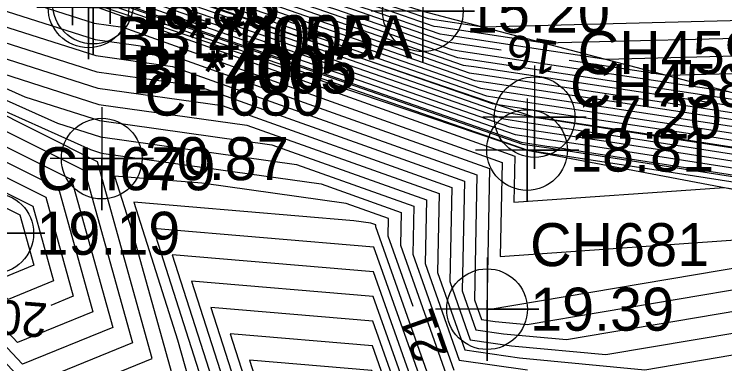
# Model space of a CAD drawing. Extents: x 2531902 to 2533249, y 715219 to 716099.
# Drawn here: x 2532709.09 to 2532750.37, y 715611.98 to 715632.29 of the extents above; entities that cross this region are included whole.
import ezdxf

# ---------------------------------------------------------------- set-up
doc = ezdxf.new("R2010")
doc.units = 0
for name, color, linetype in [('DTM Contours Major', 7, 'Continuous'), ('DTM Contours Major Text', 7, 'Continuous'), ('DTM Contours Minor', 7, 'Continuous'), ('Exist DTM Breakline', 7, 'Continuous'), ('Exist DTM Breakline Cogo Comment', 7, 'Continuous'), ('Exist DTM Breakline Cogo Elevation', 7, 'Continuous'), ('Exist DTM Breakline Cogo Number', 7, 'Continuous'), ('Exist DTM Breakline Cogo Point CELL', 7, 'Continuous'), ('Exist DTM Breakline Underwater', 7, 'Continuous'), ('Exist DTM Breakline Underwater Cogo Elevation', 7, 'Continuous'), ('Exist DTM Breakline Underwater Cogo Point CELL', 7, 'Continuous'), ('Exist DTM QL2 LIDAR Elevation Point', 7, 'Continuous'), ('Exist DTM Regular Point CELL', 7, 'Continuous'), ('Exist DTM Regular Point Cogo Elevation', 7, 'Continuous'), ('Exist DTM Regular Point Cogo Number', 7, 'Continuous'), ('Exist Hydro Stream or Body of Water', 7, 'Continuous'), ('Scratch_Level_2', 7, 'Continuous')]:
    doc.layers.add(name, color=color, linetype=linetype)

msp = doc.modelspace()

# ---------------------------------------------------------------- linework, layer by layer
at = {"layer": 'DTM Contours Major'}
for points in [[(2532737.37, 715630.195), (2532734.519, 715630.627), (2532734.167, 715630.68), (2532728.764, 715632.559), (2532713.824, 715637.321), (2532713.421, 715637.449), (2532709.196, 715638.824), (2532697.196, 715643.047), (2532697.098, 715643.082), (2532696.035, 715644.027), (2532679.899, 715666.702), (2532679.893, 715666.711), (2532679.876, 715666.752), (2532679.875, 715666.753), (2532679.797, 715667.006), (2532679.994, 715666.896), (2532680.065, 715666.76), (2532689.19, 715656.805), (2532699.24, 715647.16), (2532699.515, 715647.106)], [(2532674.529, 715657.71), (2532672.706, 715658.283), (2532669.358, 715655.677), (2532669.391, 715655.408), (2532669.64, 715655.324), (2532669.93, 715655.106), (2532682.035, 715650.435), (2532694.89, 715638.9), (2532696.316, 715638.261), (2532713.679, 715632.717), (2532713.962, 715632.678), (2532738.178, 715624.046), (2532738.122, 715621.369), (2532750.341, 715622.225), (2532752.309, 715621.919)], [(2532685.255, 715654.828), (2532691.3, 715646.332), (2532696.58, 715641.634), (2532697.068, 715641.462), (2532704.54, 715638.833), (2532713.504, 715635.916), (2532714.36, 715635.643), (2532723.662, 715632.678), (2532735.847, 715628.442), (2532736.64, 715628.322), (2532753.273, 715625.799), (2532757.258, 715625.179), (2532759.557, 715625.11), (2532775.441, 715624.38), (2532776.659, 715624.324)], [(2532683.669, 715652.707), (2532686.565, 715648.638), (2532696.063, 715640.186), (2532696.941, 715639.877), (2532699.885, 715638.841), (2532713.588, 715634.382), (2532714.896, 715633.965), (2532718.561, 715632.797), (2532737.526, 715626.203), (2532738.761, 715626.016), (2532745.314, 715625.023), (2532758.183, 715623.02), (2532765.608, 715622.796), (2532771.866, 715622.509), (2532775.8, 715622.328)], [(2532674.126, 715647.354), (2532676.074, 715645.889), (2532680.793, 715644.068), (2532685.805, 715639.571), (2532705.874, 715630.573), (2532713.943, 715627.997), (2532721.165, 715626.984), (2532734.505, 715622.229), (2532734.391, 715616.753), (2532735.587, 715613.371), (2532737.979, 715613.025), (2532743.455, 715612.508), (2532753.726, 715614.247), (2532759.739, 715613.652), (2532760.112, 715613.48)], [(2532713.794, 715641.93), (2532723.088, 715642.496), (2532736.736, 715641.742), (2532744.32, 715638.604), (2532751.762, 715638.071), (2532755.947, 715636.768), (2532756.057, 715636.734), (2532756.721, 715636.63), (2532756.752, 715636.632), (2532759.128, 715636.781), (2532769.239, 715634.791), (2532776.683, 715633.031), (2532755.339, 715628.939), (2532747.02, 715628.731), (2532741.325, 715629.595)], [(2532683.727, 715635.961), (2532692.276, 715630.998), (2532710.916, 715621.657), (2532712.519, 715615.898), (2532711.223, 715615.369)], [(2532732.259, 715615.307), (2532730.812, 715619.4), (2532730.833, 715620.412), (2532728.367, 715621.291), (2532719.991, 715622.465), (2532714.911, 715622.89), (2532715.925, 715619.72), (2532718.245, 715611.384), (2532714.855, 715610), (2532715.256, 715604.744)], [(2532732.381, 715607.491), (2532729.917, 715614.457), (2532720.511, 715615.244), (2532722.885, 715607.822), (2532723.016, 715600.82), (2532724.345, 715598.612)]]:
    msp.add_lwpolyline(points, dxfattribs=at)
at = {"layer": 'DTM Contours Minor'}
for points in [[(2532636.7, 715718.732), (2532648.882, 715711.393), (2532650.176, 715710.428), (2532650.296, 715710.159), (2532650.961, 715708.731), (2532650.355, 715708.634), (2532649.557, 715698.18), (2532650.088, 715686.722), (2532650.205, 715682.83), (2532652.525, 715675.584), (2532660.005, 715667.15), (2532660.202, 715660.027), (2532660.105, 715659.951), (2532661.242, 715650.715), (2532669.816, 715647.839), (2532679.761, 715640.359), (2532680.048, 715640.248), (2532680.354, 715639.974), (2532711.609, 715625.96), (2532714.102, 715625.164), (2532725.486, 715623.568), (2532732.302, 715621.139), (2532732.243, 715618.341), (2532734.625, 715611.607)], [(2532680.17, 715665.452), (2532695.088, 715644.488), (2532696.994, 715642.792), (2532697.17, 715642.73), (2532708.265, 715638.826), (2532713.437, 715637.143), (2532713.931, 715636.985), (2532727.744, 715632.583), (2532734.503, 715630.233), (2532734.943, 715630.166), (2532750.583, 715627.794)], [(2532680.44, 715664.202), (2532694.141, 715644.949), (2532696.891, 715642.503), (2532697.145, 715642.413), (2532707.334, 715638.828), (2532713.454, 715636.836), (2532714.038, 715636.65), (2532726.723, 715632.606), (2532734.839, 715629.785), (2532735.368, 715629.705), (2532754.145, 715626.858), (2532756.43, 715626.915), (2532765.962, 715628.742), (2532762.782, 715626.183), (2532777.586, 715625.503), (2532778.432, 715625.464), (2532781.602, 715625.476), (2532796.599, 715625.363), (2532796.712, 715625.362), (2532796.887, 715625.399), (2532820.079, 715630.296)], [(2532680.711, 715662.952), (2532693.194, 715645.41), (2532696.787, 715642.213), (2532697.119, 715642.096), (2532706.403, 715638.829), (2532713.471, 715636.529), (2532714.146, 715636.314), (2532725.703, 715632.63), (2532735.175, 715629.337), (2532735.792, 715629.244), (2532756.457, 715626.11), (2532756.888, 715626.043), (2532757.137, 715626.036), (2532776.871, 715625.128), (2532778.124, 715625.071), (2532782.819, 715625.089), (2532796.483, 715624.986), (2532796.744, 715624.984), (2532797.148, 715625.069), (2532818.278, 715629.531)], [(2532680.982, 715661.701), (2532692.247, 715645.871), (2532696.684, 715641.923), (2532697.094, 715641.779), (2532705.471, 715638.831), (2532713.487, 715636.222), (2532714.253, 715635.978), (2532724.683, 715632.654), (2532735.511, 715628.89), (2532736.216, 715628.783), (2532754.865, 715625.955), (2532757.073, 715625.611), (2532758.347, 715625.573), (2532776.156, 715624.754), (2532777.816, 715624.678), (2532784.036, 715624.702), (2532796.367, 715624.609), (2532796.776, 715624.606), (2532797.409, 715624.739), (2532816.477, 715628.766)], [(2532681.524, 715659.201), (2532690.353, 715646.793), (2532696.477, 715641.344), (2532697.043, 715641.145), (2532703.609, 715638.834), (2532713.521, 715635.609), (2532714.467, 715635.307), (2532722.642, 715632.701), (2532736.183, 715627.994), (2532737.064, 715627.861), (2532751.681, 715625.644), (2532757.443, 715624.748), (2532760.767, 715624.647), (2532774.726, 715624.006), (2532777.201, 715623.892), (2532786.471, 715623.928), (2532796.136, 715623.855), (2532796.841, 715623.85), (2532797.93, 715624.08), (2532812.876, 715627.235)], [(2532681.795, 715657.95), (2532689.406, 715647.255), (2532696.373, 715641.055), (2532697.018, 715640.828), (2532702.678, 715638.836), (2532713.538, 715635.302), (2532714.575, 715634.971), (2532721.622, 715632.725), (2532736.519, 715627.547), (2532737.489, 715627.399), (2532750.09, 715625.489), (2532757.628, 715624.316), (2532761.978, 715624.184), (2532774.011, 715623.631), (2532776.893, 715623.499), (2532787.688, 715623.54), (2532796.02, 715623.478), (2532796.873, 715623.471), (2532798.191, 715623.75), (2532811.075, 715626.47)], [(2532682.066, 715656.7), (2532688.459, 715647.716), (2532696.27, 715640.765), (2532696.992, 715640.511), (2532701.747, 715638.838), (2532713.554, 715634.995), (2532714.682, 715634.636), (2532720.601, 715632.749), (2532736.855, 715627.099), (2532737.913, 715626.938), (2532748.498, 715625.333), (2532757.813, 715623.884), (2532763.188, 715623.722), (2532773.296, 715623.257), (2532776.585, 715623.106), (2532788.906, 715623.153), (2532795.904, 715623.101), (2532796.905, 715623.093), (2532798.452, 715623.42), (2532809.275, 715625.705)], [(2532682.336, 715655.45), (2532687.512, 715648.177), (2532696.166, 715640.475), (2532696.967, 715640.194), (2532700.816, 715638.839), (2532713.571, 715634.688), (2532714.789, 715634.3), (2532719.581, 715632.773), (2532737.191, 715626.651), (2532738.337, 715626.477), (2532746.906, 715625.178), (2532757.998, 715623.452), (2532764.398, 715623.259), (2532772.581, 715622.883), (2532776.277, 715622.713), (2532790.123, 715622.766), (2532795.789, 715622.724), (2532796.937, 715622.715), (2532798.713, 715623.09), (2532807.474, 715624.94)], [(2532681.549, 715654.816), (2532682.878, 715652.949), (2532685.618, 715649.099), (2532695.959, 715639.896), (2532696.916, 715639.56), (2532698.953, 715638.843), (2532713.604, 715634.075), (2532715.003, 715633.629), (2532717.54, 715632.82), (2532737.862, 715625.756), (2532739.186, 715625.555), (2532743.722, 715624.867), (2532758.368, 715622.588), (2532766.819, 715622.333), (2532771.15, 715622.134), (2532775.661, 715621.927), (2532792.558, 715621.992), (2532795.557, 715621.969), (2532797.001, 715621.958), (2532799.234, 715622.43), (2532803.873, 715623.409)], [(2532681.7, 715653.735), (2532683.149, 715651.699), (2532684.671, 715649.56), (2532695.856, 715639.607), (2532696.89, 715639.243), (2532698.022, 715638.844), (2532713.621, 715633.768), (2532715.111, 715633.293), (2532716.52, 715632.844), (2532738.198, 715625.308), (2532739.61, 715625.094), (2532742.13, 715624.712), (2532758.553, 715622.157), (2532768.029, 715621.871), (2532770.435, 715621.76), (2532775.353, 715621.534), (2532793.775, 715621.605), (2532795.442, 715621.592), (2532797.033, 715621.58), (2532799.495, 715622.1), (2532802.072, 715622.644)], [(2532681.851, 715652.654), (2532683.42, 715650.449), (2532683.724, 715650.021), (2532695.752, 715639.317), (2532696.865, 715638.926), (2532697.091, 715638.846), (2532713.638, 715633.461), (2532715.218, 715632.958), (2532715.5, 715632.868), (2532738.534, 715624.86), (2532740.034, 715624.633), (2532740.538, 715624.556), (2532758.738, 715621.725), (2532769.239, 715621.408), (2532769.72, 715621.386), (2532775.045, 715621.141), (2532794.993, 715621.218), (2532795.326, 715621.215), (2532797.066, 715621.202), (2532799.756, 715621.77), (2532800.271, 715621.879), (2532825.827, 715627.523)], [(2532682.001, 715651.572), (2532682.777, 715650.482), (2532690.122, 715643.946), (2532695.649, 715639.028), (2532696.16, 715638.848), (2532705.016, 715635.966), (2532713.655, 715633.155), (2532714.479, 715632.892), (2532737.701, 715624.819), (2532738.87, 715624.413), (2532738.946, 715624.401), (2532745.88, 715623.322), (2532758.923, 715621.293), (2532766.449, 715621.066), (2532770.449, 715620.945), (2532774.737, 715620.748), (2532790.801, 715620.81), (2532796.21, 715620.83), (2532797.098, 715620.824), (2532798.47, 715621.114), (2532803.901, 715622.313)], [(2532681.787, 715649.161), (2532693.073, 715639.034), (2532698.228, 715636.723), (2532713.731, 715631.773), (2532715.403, 715631.539), (2532737.443, 715623.682), (2532737.33, 715618.219), (2532754.561, 715619.426), (2532758.918, 715620.164), (2532759.276, 715620.128), (2532759.832, 715619.872), (2532762.685, 715620.327), (2532772.87, 715620.019), (2532774.121, 715619.962), (2532778.811, 715619.98), (2532783.105, 715619.996), (2532796.357, 715619.409), (2532797.382, 715619.588), (2532797.854, 715619.53), (2532798.133, 715619.713), (2532799.275, 715620.232), (2532807.884, 715622.457)], [(2532713.029, 715641.979), (2532716.741, 715641.26), (2532724.694, 715641.744), (2532736.373, 715641.099), (2532747.184, 715636.626), (2532755.897, 715636.002), (2532769.535, 715632.777), (2532754.794, 715629.951), (2532743.458, 715629.668), (2532734.095, 715631.088), (2532733.831, 715631.128), (2532729.784, 715632.535), (2532713.717, 715637.657), (2532713.404, 715637.756), (2532710.127, 715638.823), (2532697.221, 715643.364), (2532697.201, 715643.371), (2532696.982, 715643.566), (2532693.501, 715648.458), (2532695.572, 715646.199), (2532697.642, 715644.211), (2532704.931, 715642.789), (2532712.237, 715641.951), (2532713.029, 715641.979)], [(2532681.538, 715647.888), (2532691.256, 715639.168), (2532700.139, 715635.185), (2532713.784, 715630.829), (2532716.843, 715630.4), (2532736.709, 715623.319), (2532736.539, 715615.164), (2532736.549, 715615.135), (2532736.57, 715615.132), (2532736.617, 715615.128), (2532757.62, 715618.685), (2532759.392, 715618.509), (2532762.143, 715617.241), (2532773.58, 715619.066), (2532773.975, 715619.47), (2532774.163, 715619.461), (2532795.746, 715618.505), (2532797.59, 715618.827), (2532798.439, 715618.722), (2532798.941, 715619.051), (2532800.996, 715619.985), (2532816.486, 715623.99)], [(2532681.29, 715646.615), (2532689.439, 715639.303), (2532702.051, 715633.648), (2532713.837, 715629.885), (2532718.284, 715629.262), (2532735.974, 715622.956), (2532735.823, 715615.694), (2532736.229, 715614.547), (2532737.039, 715614.43), (2532738.896, 715614.255), (2532756.322, 715617.206), (2532759.507, 715616.89), (2532764.454, 715614.609), (2532771.942, 715615.804), (2532774.584, 715618.512), (2532775.847, 715618.455), (2532795.135, 715617.6), (2532797.797, 715618.066), (2532799.024, 715617.915), (2532799.75, 715618.389), (2532802.717, 715619.738)], [(2532681.042, 715645.341), (2532687.622, 715639.437), (2532703.963, 715632.11), (2532713.89, 715628.941), (2532719.724, 715628.123), (2532735.24, 715622.592), (2532735.107, 715616.223), (2532735.908, 715613.959), (2532737.509, 715613.727), (2532741.176, 715613.381), (2532755.024, 715615.726), (2532759.623, 715615.271), (2532766.765, 715611.978), (2532770.304, 715612.543), (2532775.194, 715617.554), (2532777.532, 715617.449), (2532794.524, 715616.696), (2532798.005, 715617.305), (2532799.61, 715617.107), (2532800.558, 715617.728), (2532804.439, 715619.492)], [(2532680.545, 715642.795), (2532683.988, 715639.705), (2532707.786, 715629.035), (2532713.996, 715627.053), (2532722.605, 715625.845), (2532733.771, 715621.865), (2532733.675, 715617.282), (2532735.267, 715612.783), (2532738.448, 715612.322), (2532745.734, 715611.634), (2532752.429, 715612.768), (2532759.855, 715612.033), (2532764.702, 715609.798)], [(2532716.602, 715641.188), (2532719.688, 715640.59), (2532726.3, 715640.993), (2532736.01, 715640.456), (2532750.047, 715634.648), (2532754.857, 715634.304), (2532762.386, 715632.523), (2532754.248, 715630.963), (2532739.896, 715630.605), (2532733.671, 715631.549), (2532733.495, 715631.576), (2532730.804, 715632.511), (2532713.61, 715637.992), (2532713.387, 715638.063), (2532711.058, 715638.821), (2532700.961, 715642.374), (2532712.558, 715641.045), (2532716.602, 715641.188)], [(2532720.174, 715640.397), (2532722.634, 715639.92), (2532727.906, 715640.241), (2532735.646, 715639.814), (2532752.91, 715632.67), (2532753.818, 715632.605), (2532755.238, 715632.27), (2532753.703, 715631.975), (2532736.334, 715631.542), (2532733.246, 715632.01), (2532733.159, 715632.024), (2532731.825, 715632.487), (2532713.502, 715638.328), (2532713.37, 715638.37), (2532711.989, 715638.819), (2532706.002, 715640.926), (2532712.879, 715640.138), (2532720.174, 715640.397)], [(2532680.227, 715639.754), (2532680.748, 715639.451), (2532713.166, 715623.206), (2532715.954, 715613.19), (2532709.845, 715610.696), (2532701.165, 715619.935), (2532698.662, 715621.232), (2532689.962, 715621.442), (2532684.167, 715629.759), (2532680.227, 715639.754)], [(2532682.171, 715639.84), (2532709.697, 715627.498), (2532714.049, 715626.108), (2532724.046, 715624.707), (2532733.036, 715621.502), (2532732.959, 715617.812), (2532734.946, 715612.195), (2532738.918, 715611.62)], [(2532681.394, 715638.49), (2532684.591, 715636.634), (2532712.416, 715622.69), (2532714.809, 715614.092), (2532709.566, 715611.952), (2532702.115, 715619.882), (2532697.57, 715622.237), (2532689.936, 715622.421), (2532684.851, 715629.719), (2532681.394, 715638.49)], [(2532682.561, 715637.226), (2532688.433, 715633.816), (2532711.666, 715622.174), (2532713.664, 715614.995), (2532709.286, 715613.208), (2532703.065, 715619.83), (2532696.478, 715623.242), (2532689.91, 715623.401), (2532685.535, 715629.68), (2532682.561, 715637.226)], [(2532684.894, 715634.697), (2532696.119, 715628.18), (2532710.166, 715621.141), (2532711.374, 715616.801), (2532708.727, 715615.72), (2532704.965, 715619.724), (2532694.294, 715625.252), (2532689.858, 715625.359), (2532686.903, 715629.6), (2532684.894, 715634.697)], [(2532686.061, 715633.433), (2532699.961, 715625.363), (2532709.416, 715620.625), (2532710.229, 715617.704), (2532708.447, 715616.976), (2532705.916, 715619.671), (2532693.202, 715626.258), (2532689.832, 715626.339), (2532687.587, 715629.561), (2532686.061, 715633.433)], [(2532711.498, 715610), (2532717.1, 715612.287), (2532713.917, 715623.722), (2532704.007, 715628.688), (2532713.521, 715624.423), (2532714.154, 715624.22), (2532726.927, 715622.429), (2532731.567, 715620.775), (2532731.527, 715618.87), (2532734.305, 715611.019)], [(2532721.419, 715597.161), (2532729.966, 715582.968), (2532738.612, 715591.711), (2532738.691, 715600.338), (2532738.752, 715609.106), (2532733.664, 715609.843), (2532730.096, 715619.929), (2532730.098, 715620.049), (2532729.808, 715620.152), (2532728.821, 715620.29), (2532716.031, 715621.361), (2532718.583, 715613.379), (2532719.39, 715610.481), (2532718.211, 715610), (2532718.89, 715601.11)], [(2532733.343, 715609.255), (2532729.981, 715618.758), (2532717.151, 715619.832), (2532720.389, 715609.707), (2532720.567, 715600.154), (2532729.947, 715584.576), (2532737.887, 715592.604), (2532737.96, 715600.526), (2532738.016, 715608.578), (2532733.343, 715609.255)], [(2532733.022, 715608.667), (2532729.96, 715617.324), (2532718.271, 715618.303), (2532721.221, 715609.078), (2532721.383, 715600.376), (2532729.929, 715586.184), (2532737.162, 715593.498), (2532737.228, 715600.715), (2532737.279, 715608.05), (2532733.022, 715608.667)], [(2532732.702, 715608.079), (2532729.938, 715615.891), (2532719.391, 715616.774), (2532722.053, 715608.45), (2532722.199, 715600.598), (2532729.91, 715587.792), (2532736.437, 715594.391), (2532736.497, 715600.904), (2532736.543, 715607.522), (2532732.702, 715608.079)], [(2532732.06, 715606.903), (2532729.895, 715613.023), (2532721.632, 715613.715), (2532723.717, 715607.194), (2532723.832, 715601.041), (2532729.873, 715591.008), (2532734.987, 715596.179), (2532735.034, 715601.281), (2532735.07, 715606.467), (2532732.06, 715606.903)], [(2532731.74, 715606.315), (2532729.874, 715611.59), (2532722.752, 715612.186), (2532724.549, 715606.566), (2532724.648, 715601.263), (2532729.855, 715592.616), (2532734.262, 715597.072), (2532734.302, 715601.47), (2532734.333, 715605.939), (2532731.74, 715606.315)]]:
    msp.add_lwpolyline(points, dxfattribs=at)
at = {"layer": 'Exist DTM Breakline'}
msp.add_lwpolyline([(2532713.668, 715632.91), (2532738.883, 715624.395), (2532759.246, 715620.539), (2532773.868, 715619.638), (2532797.122, 715620.541), (2532830.298, 715626.45), (2532834.772, 715629.357), (2532845.901, 715630.257), (2532852.301, 715627.724), (2532853.675, 715626.881), (2532873.942, 715617.949), (2532888.735, 715612.988), (2532909.367, 715604.653), (2532924.285, 715597.984), (2532944.343, 715591.433), (2532962.6, 715582.573), (2532991.856, 715569.195), (2533016.156, 715554.384)], dxfattribs=at)
at = {"layer": 'Exist DTM Breakline Cogo Point CELL'}
for points in [[(2532712.47, 715637.655), (2532712.47, 715631.655), (2532712.47, 715634.655), (2532715.47, 715634.655), (2532709.47, 715634.655)], [(2532714.664, 715637.736), (2532714.664, 715631.736), (2532714.664, 715634.736), (2532717.664, 715634.736), (2532711.664, 715634.736)], [(2532713.402, 715635.687), (2532713.402, 715629.687), (2532713.402, 715632.687), (2532716.402, 715632.687), (2532710.402, 715632.687)], [(2532713.668, 715635.91), (2532713.668, 715629.91), (2532713.668, 715632.91), (2532716.668, 715632.91), (2532710.668, 715632.91)], [(2532739.321, 715629.311), (2532739.321, 715623.311), (2532739.321, 715626.311), (2532742.321, 715626.311), (2532736.321, 715626.311)], [(2532738.883, 715627.395), (2532738.883, 715621.395), (2532738.883, 715624.395), (2532741.883, 715624.395), (2532735.883, 715624.395)]]:
    msp.add_lwpolyline(points, dxfattribs=at)
for centre in [(2532713.668, 715632.91), (2532713.402, 715632.687), (2532739.321, 715626.311), (2532738.883, 715624.395)]:
    msp.add_circle(centre, 2.344, dxfattribs=at)
at = {"layer": 'Exist DTM Breakline Underwater'}
msp.add_lwpolyline([(2532642.404, 715750.56), (2532658.799, 715717.787), (2532669.356, 715695.376), (2532679.885, 715666.767), (2532697.228, 715643.446), (2532713.346, 715638.817), (2532732.829, 715632.464), (2532756.843, 715626.148), (2532779.072, 715626.28), (2532796.688, 715625.652), (2532823.757, 715631.859), (2532837.11, 715635.289), (2532855.521, 715634.196), (2532877.341, 715623.453), (2532903.322, 715612.979), (2532923.748, 715606.844), (2532938.002, 715599.697), (2532947.164, 715595.611), (2532973.382, 715584.595), (2532998.348, 715572.794), (2533019.077, 715559.415)], dxfattribs=at)
at = {"layer": 'Exist DTM Breakline Underwater Cogo Point CELL'}
msp.add_lwpolyline([(2532732.829, 715635.464), (2532732.829, 715629.464), (2532732.829, 715632.464), (2532735.829, 715632.464), (2532729.829, 715632.464)], dxfattribs=at)
msp.add_circle((2532732.829, 715632.464), 2.344, dxfattribs=at)
at = {"layer": 'Exist DTM QL2 LIDAR Elevation Point'}
msp.add_line((2532730, 715620), (2532730, 715620), dxfattribs=at)
at = {"layer": 'Exist DTM Regular Point CELL'}
for points in [[(2532714.172, 715626.898), (2532714.172, 715620.898), (2532714.172, 715623.898), (2532717.172, 715623.898), (2532711.172, 715623.898)], [(2532707.871, 715622.562), (2532707.871, 715616.562), (2532707.871, 715619.562), (2532710.871, 715619.562), (2532704.871, 715619.562)], [(2532736.558, 715618.151), (2532736.558, 715612.151), (2532736.558, 715615.151), (2532739.558, 715615.151), (2532733.558, 715615.151)]]:
    msp.add_lwpolyline(points, dxfattribs=at)
for centre in [(2532714.172, 715623.898), (2532707.871, 715619.562), (2532736.558, 715615.151)]:
    msp.add_circle(centre, 2.344, dxfattribs=at)
at = {"layer": 'Exist Hydro Stream or Body of Water'}
msp.add_lwpolyline([(2532681.888, 715652.383), (2532683.487, 715650.136), (2532695.727, 715639.245), (2532696.858, 715638.846), (2532713.642, 715633.385), (2532715.245, 715632.874), (2532738.618, 715624.748), (2532740.14, 715624.518), (2532758.785, 715621.617), (2532769.542, 715621.292), (2532774.968, 715621.043), (2532795.297, 715621.121), (2532797.074, 715621.107), (2532799.821, 715621.688), (2532825.866, 715627.44)], dxfattribs=at)
at = {"layer": 'Scratch_Level_2'}
msp.add_lwpolyline([(2532714.664, 715634.736), (2532739.321, 715626.311), (2532759.871, 715623.13), (2532773.772, 715622.161), (2532797.407, 715622.564), (2532828.795, 715628.744), (2532834.22, 715630.983), (2532845.975, 715632.207), (2532853.028, 715629.31), (2532854.542, 715628.512), (2532875.028, 715620.214), (2532888.893, 715614.569), (2532909.676, 715606.722), (2532925.335, 715600.738), (2532945.352, 715592.461), (2532962.769, 715583.896), (2532993.283, 715570.726), (2533017.454, 715556.427)], dxfattribs=at)

# ---------------------------------------------------------------- texts
at = {"layer": 'DTM Contours Major Text'}
for s, rotation, p in [('16', 171.3774, (2532740.782, 715630.689)), ('20', 175.4356, (2532711.076, 715615.48)), ('21', 109.4812, (2532734.3, 715612.537))]:
    msp.add_text(s, height=2, rotation=rotation, dxfattribs=at).set_placement(p)
at = {"layer": 'Exist DTM Breakline Cogo Comment'}
for s, p in [('BL*4005A', (2532714.97, 715629.655)), ('BL*4005A', (2532717.164, 715629.736)), ('BL*4005', (2532715.902, 715627.687)), ('BL*4005', (2532716.168, 715627.91))]:
    msp.add_text(s, height=2.5, dxfattribs=at).set_placement(p)
at = {"layer": 'Exist DTM Breakline Cogo Elevation'}
for s, p in [('18.86', (2532715.902, 715631.437)), ('18.96', (2532716.168, 715631.66)), ('17.20', (2532741.821, 715625.061)), ('18.81', (2532741.383, 715623.145))]:
    msp.add_text(s, height=2.5, dxfattribs=at).set_placement(p)
at = {"layer": 'Exist DTM Breakline Cogo Number'}
for s, p in [('CH459', (2532741.821, 715628.811)), ('CH458', (2532741.383, 715626.895))]:
    msp.add_text(s, height=2.5, dxfattribs=at).set_placement(p)
at = {"layer": 'Exist DTM Breakline Underwater Cogo Elevation'}
msp.add_text('15.20', height=2.5, dxfattribs=at).set_placement((2532735.329, 715631.214))
at = {"layer": 'Exist DTM Regular Point Cogo Elevation'}
for s, p in [('20.87', (2532716.672, 715622.648)), ('19.19', (2532710.371, 715618.312)), ('19.39', (2532739.058, 715613.901))]:
    msp.add_text(s, height=2.5, dxfattribs=at).set_placement(p)
at = {"layer": 'Exist DTM Regular Point Cogo Number'}
for s, p in [('CH680', (2532716.672, 715626.398)), ('CH679', (2532710.371, 715622.062)), ('CH681', (2532739.058, 715617.651))]:
    msp.add_text(s, height=2.5, dxfattribs=at).set_placement(p)

doc.saveas('drawing.dxf')
